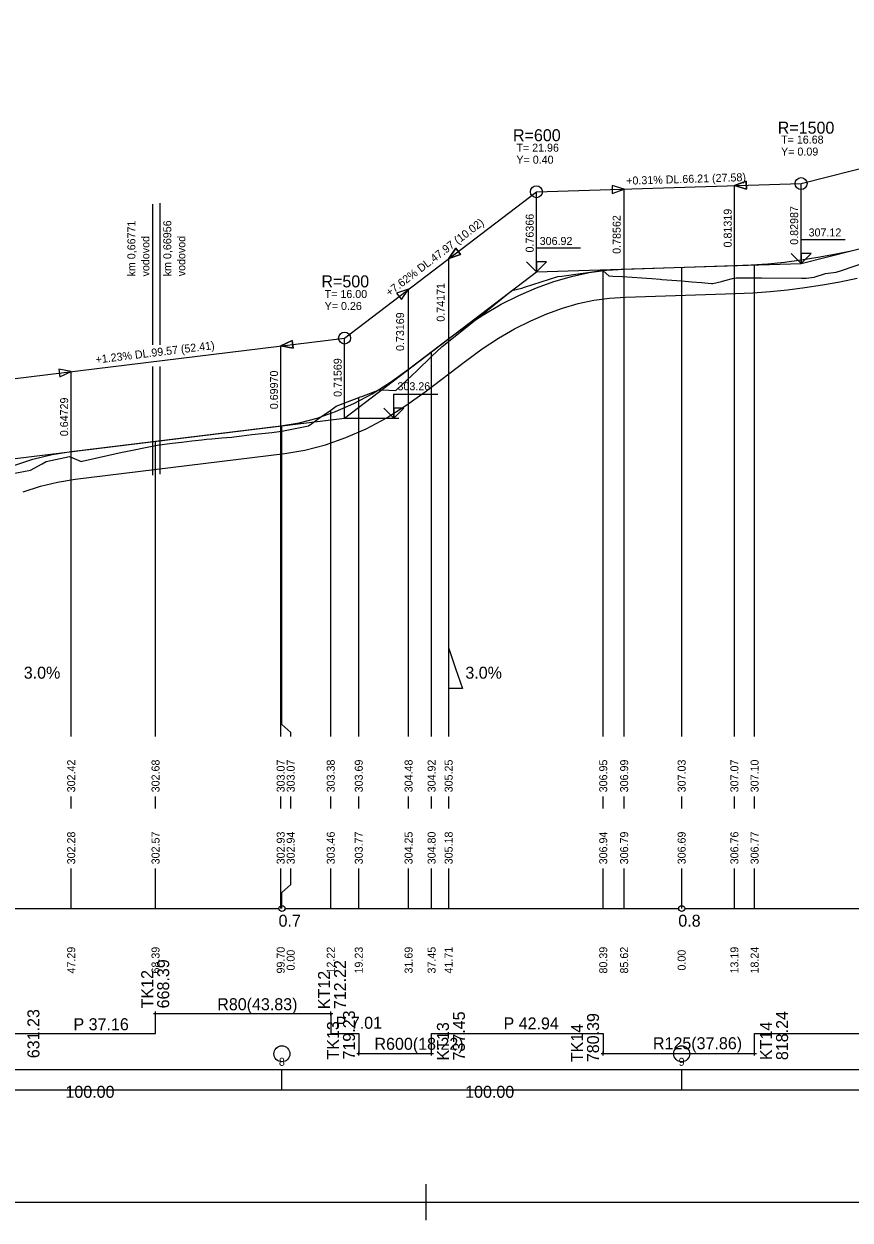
# Model space of a CAD drawing. Extents: x 1301 to 1448, y 183 to 228.
# Drawn here: x 1374.89 to 1395.56, y 182.54 to 212.44 of the extents above; entities that cross this region are included whole.
import ezdxf

# ---------------------------------------------------------------- set-up
doc = ezdxf.new("R2010")
doc.units = 0
for name, color, linetype in [('KOTA', 7, 'Continuous'), ('NOVY_STAV', 7, 'Continuous'), ('NS_OBLOUK', 7, 'Continuous'), ('REZY_PO', 7, 'Continuous'), ('SESTAVY_REZU_PO', 7, 'Continuous'), ('SKLONOVE_POMERY', 7, 'Continuous'), ('SMEROVE_POMERY', 7, 'Continuous'), ('SMEROVE_POMERY_KOD', 7, 'Continuous'), ('SVK_STAT', 7, 'Continuous'), ('u_drenaz', 7, 'Continuous'), ('u_popis', 7, 'Continuous'), ('u_pricne_rezy', 7, 'Continuous'), ('x_formát_rám', 7, 'Continuous')]:
    doc.layers.add(name, color=color, linetype=linetype)

msp = doc.modelspace()

# ---------------------------------------------------------------- linework, layer by layer
at = {"layer": 'KOTA'}
msp.add_line((1382.912, 202.588), (1384.266, 202.588), dxfattribs=at)
for points in [[(1394.33, 206.448), (1394.08, 206.698), (1394.33, 206.448), (1394.33, 207.048), (1395.43, 207.048)], [(1387.709, 206.246), (1387.459, 206.496), (1387.709, 206.246), (1387.709, 206.846), (1388.809, 206.846)], [(1394.33, 206.698), (1394.33, 206.448), (1394.58, 206.698), (1394.33, 206.698)], [(1394.33, 206.448), (1394.58, 206.698), (1394.33, 206.698)], [(1387.709, 206.496), (1387.709, 206.246), (1387.959, 206.496), (1387.709, 206.496)], [(1387.709, 206.246), (1387.959, 206.496), (1387.709, 206.496)], [(1394.33, 206.448), (1394.33, 206.448)], [(1387.709, 206.246), (1387.709, 206.246)], [(1384.145, 202.588), (1383.895, 202.838), (1384.145, 202.588), (1384.145, 203.188), (1385.245, 203.188)], [(1384.145, 202.838), (1384.145, 202.588), (1384.395, 202.838), (1384.145, 202.838)], [(1384.145, 202.588), (1384.395, 202.838), (1384.145, 202.838)], [(1384.145, 202.588), (1384.145, 202.588)]]:
    msp.add_lwpolyline(points, dxfattribs=at)
at = {"layer": 'NOVY_STAV'}
for points in [[(1371.343, 199.496), (1372.956, 201.369), (1382.912, 202.588), (1387.709, 206.246), (1394.33, 206.448), (1402.893, 208.614), (1408.521, 213.539), (1416.937, 214.971), (1425.443, 212.807)], [(1394.33, 208.448), (1402.893, 210.614)], [(1387.709, 208.246), (1394.33, 208.448)], [(1394.33, 206.448), (1394.33, 208.448)], [(1382.912, 204.588), (1387.709, 208.246)], [(1387.709, 206.246), (1387.709, 208.246)], [(1374.633, 201.402), (1375.113, 201.556), (1375.592, 201.672), (1376.072, 201.75), (1381.312, 202.392), (1381.77, 202.469), (1382.227, 202.588), (1382.684, 202.748), (1383.141, 202.951), (1383.598, 203.195), (1384.055, 203.48), (1384.512, 203.808), (1385.514, 204.572), (1385.953, 204.89), (1386.392, 205.177), (1386.831, 205.431), (1387.27, 205.654), (1387.709, 205.844), (1388.148, 206.002), (1388.587, 206.128), (1389.026, 206.222), (1389.465, 206.283), (1389.904, 206.313), (1392.662, 206.397), (1393.079, 206.416), (1393.496, 206.446), (1393.913, 206.487), (1394.33, 206.541), (1394.747, 206.606), (1395.164, 206.682), (1395.581, 206.77)], [(1372.956, 203.369), (1382.912, 204.588)], [(1382.912, 202.588), (1382.912, 204.588)]]:
    msp.add_lwpolyline(points, dxfattribs=at)
for centre in [(1394.33, 208.448), (1387.709, 208.246), (1382.912, 204.588)]:
    msp.add_circle(centre, 0.15, dxfattribs=at)
at = {"layer": 'NS_OBLOUK'}
for points in [[(1392.662, 208.397), (1392.965, 208.306), (1392.959, 208.506), (1392.662, 208.397)], [(1389.608, 208.204), (1389.905, 208.313), (1389.602, 208.404), (1389.608, 208.204)], [(1389.905, 206.313), (1389.905, 208.313)], [(1392.662, 206.397), (1392.662, 208.397)], [(1385.514, 206.572), (1385.813, 206.674), (1385.691, 206.833), (1385.514, 206.572)], [(1385.514, 204.572), (1385.514, 206.572)], [(1384.334, 205.547), (1384.512, 205.808), (1384.213, 205.706), (1384.334, 205.547)], [(1384.512, 203.808), (1384.512, 205.808)], [(1381.312, 204.392), (1381.622, 204.33), (1381.598, 204.528), (1381.312, 204.392)], [(1381.312, 202.392), (1381.312, 204.392)], [(1375.786, 203.615), (1376.072, 203.75), (1375.762, 203.813), (1375.786, 203.615)], [(1376.072, 201.75), (1376.072, 203.75)]]:
    msp.add_lwpolyline(points, dxfattribs=at)
for points in [[(1392.662, 208.397), (1392.959, 208.506), (1392.965, 208.306)], [(1389.905, 208.313), (1389.602, 208.404), (1389.608, 208.204)], [(1385.514, 206.572), (1385.691, 206.833), (1385.813, 206.674)], [(1384.512, 205.808), (1384.213, 205.706), (1384.334, 205.547)], [(1381.312, 204.392), (1381.598, 204.528), (1381.622, 204.33)], [(1376.072, 203.75), (1375.762, 203.813), (1375.786, 203.615)]]:
    msp.add_lwpolyline(points, close=True, dxfattribs=at)
at = {"layer": 'REZY_PO'}
msp.add_lwpolyline([(1374.524, 201.187), (1375.049, 201.283), (1375.343, 201.446), (1375.443, 201.501), (1376.027, 201.626), (1376.324, 201.504), (1376.343, 201.508), (1377.343, 201.73), (1377.4, 201.743), (1378.182, 201.901), (1378.182, 201.901), (1378.182, 201.901), (1378.262, 201.917), (1378.283, 201.921), (1378.343, 201.928), (1378.593, 201.958), (1378.843, 201.987), (1379.093, 202.016), (1379.343, 202.044), (1379.457, 202.057), (1379.593, 202.069), (1379.843, 202.091), (1380.093, 202.112), (1380.14, 202.115), (1380.343, 202.141), (1380.593, 202.172), (1380.843, 202.201), (1381.093, 202.229), (1381.27, 202.248), (1381.343, 202.262), (1381.593, 202.309), (1381.843, 202.359), (1382.007, 202.393), (1382.093, 202.454), (1382.343, 202.63), (1382.454, 202.709), (1382.565, 202.788), (1382.565, 202.788), (1382.565, 202.788), (1382.702, 202.885), (1383.266, 203.1), (1383.304, 203.114), (1383.343, 203.129), (1383.774, 203.296), (1383.843, 203.292), (1384.193, 203.273), (1384.343, 203.415), (1384.715, 203.769), (1385.088, 204.122), (1385.343, 204.365), (1385.351, 204.372), (1386.343, 205.171), (1387.091, 205.774), (1387.343, 205.838), (1387.415, 205.856), (1388.247, 206.124), (1388.343, 206.138), (1389.343, 206.278), (1389.367, 206.281), (1389.382, 206.269), (1389.524, 206.144), (1389.622, 206.138), (1389.862, 206.123), (1390.103, 206.107), (1390.343, 206.09), (1390.593, 206.072), (1390.807, 206.056), (1390.843, 206.053), (1391.093, 206.035), (1391.343, 206.016), (1391.343, 206.016), (1391.593, 205.996), (1391.843, 205.974), (1392.093, 205.952), (1392.12, 205.95), (1392.343, 206.003), (1392.421, 206.022), (1392.618, 206.072), (1392.708, 206.096), (1392.892, 206.095), (1393.167, 206.093), (1393.343, 206.092), (1394.343, 206.086), (1394.458, 206.086), (1394.655, 206.113), (1394.942, 206.197), (1395.209, 206.233), (1395.343, 206.278), (1396.343, 206.618)], dxfattribs=at)
at = {"layer": 'SESTAVY_REZU_PO'}
for points in [[(1371.418, 190.326), (1381.268, 190.326)], [(1381.418, 190.326), (1391.268, 190.326)], [(1391.418, 190.326), (1401.268, 190.326)]]:
    msp.add_lwpolyline(points, dxfattribs=at)
for centre in [(1381.343, 190.326), (1391.343, 190.326)]:
    msp.add_circle(centre, 0.075, dxfattribs=at)
at = {"layer": 'SKLONOVE_POMERY'}
msp.add_lwpolyline([(1385.514, 195.826), (1385.514, 196.826), (1385.514, 196.826), (1385.689, 196.326), (1385.864, 195.826), (1385.514, 195.826)], dxfattribs=at)
at = {"layer": 'SMEROVE_POMERY'}
msp.add_lwpolyline([(1374.466, 187.204), (1378.182, 187.204), (1378.182, 187.704), (1382.565, 187.704), (1382.565, 187.204), (1383.266, 187.204), (1383.266, 186.704), (1385.088, 186.704), (1385.088, 187.204), (1389.382, 187.204), (1389.382, 186.704), (1393.167, 186.704), (1393.167, 187.204), (1401.761, 187.204)], dxfattribs=at)
at = {"layer": 'SMEROVE_POMERY_KOD'}
for points in [[(1378.132, 187.704), (1378.232, 187.704)], [(1378.182, 187.654), (1378.182, 187.754)], [(1382.515, 187.704), (1382.615, 187.704)], [(1382.565, 187.654), (1382.565, 187.754)], [(1383.216, 186.704), (1383.316, 186.704)], [(1383.266, 186.654), (1383.266, 186.754)], [(1385.038, 186.704), (1385.138, 186.704)], [(1385.088, 186.654), (1385.088, 186.754)], [(1389.332, 186.704), (1389.432, 186.704)], [(1389.382, 186.654), (1389.382, 186.754)], [(1393.117, 186.704), (1393.217, 186.704)], [(1393.167, 186.654), (1393.167, 186.754)]]:
    msp.add_lwpolyline(points, dxfattribs=at)
at = {"layer": 'SVK_STAT'}
for points in [[(1391.343, 194.626), (1391.343, 206.357)], [(1392.662, 194.626), (1392.662, 206.397)], [(1393.167, 194.626), (1393.167, 206.422)], [(1389.382, 194.626), (1389.382, 206.271)], [(1389.905, 194.626), (1389.905, 206.313)], [(1385.514, 194.626), (1385.514, 204.572)], [(1385.088, 194.626), (1385.088, 204.247)], [(1384.512, 194.626), (1384.512, 203.808)], [(1383.266, 194.626), (1383.266, 203.1)], [(1382.565, 194.626), (1382.565, 202.788)], [(1381.312, 194.626), (1381.312, 202.392)], [(1381.562, 194.626), (1381.562, 194.726), (1381.343, 194.926), (1381.343, 202.397)], [(1378.182, 194.626), (1378.182, 202.009)], [(1376.072, 194.626), (1376.072, 201.75)], [(1376.072, 192.826), (1376.072, 193.126)], [(1378.182, 192.826), (1378.182, 193.126)], [(1381.312, 192.826), (1381.312, 193.126)], [(1381.562, 192.826), (1381.562, 193.126)], [(1382.565, 192.826), (1382.565, 193.126)], [(1383.266, 192.826), (1383.266, 193.126)], [(1384.512, 192.826), (1384.512, 193.126)], [(1385.088, 192.826), (1385.088, 193.126)], [(1385.514, 192.826), (1385.514, 193.126)], [(1389.382, 192.826), (1389.382, 193.126)], [(1389.905, 192.826), (1389.905, 193.126)], [(1391.343, 192.826), (1391.343, 193.126)], [(1392.662, 192.826), (1392.662, 193.126)], [(1393.167, 192.826), (1393.167, 193.126)], [(1376.072, 190.326), (1376.072, 191.326)], [(1378.182, 190.326), (1378.182, 191.326)], [(1381.312, 190.326), (1381.312, 191.326)], [(1381.343, 190.326), (1381.343, 190.726), (1381.562, 190.926), (1381.562, 191.326)], [(1382.565, 190.326), (1382.565, 191.326)], [(1383.266, 190.326), (1383.266, 191.326)], [(1384.512, 190.326), (1384.512, 191.326)], [(1385.088, 190.326), (1385.088, 191.326)], [(1385.514, 190.326), (1385.514, 191.326)], [(1389.382, 190.326), (1389.382, 191.326)], [(1389.905, 190.326), (1389.905, 191.326)], [(1391.343, 190.326), (1391.343, 191.326)], [(1392.662, 190.326), (1392.662, 191.326)], [(1393.167, 190.326), (1393.167, 191.326)]]:
    msp.add_lwpolyline(points, dxfattribs=at)
at = {"layer": 'u_drenaz'}
msp.add_lwpolyline([(1374.872, 200.743), (1375.303, 200.882), (1375.731, 200.986), (1376.17, 201.057), (1381.413, 201.699), (1381.916, 201.784), (1382.431, 201.918), (1382.942, 202.097), (1383.448, 202.321), (1383.949, 202.588), (1384.445, 202.899), (1384.928, 203.245), (1385.931, 204.01), (1386.35, 204.314), (1386.759, 204.581), (1387.165, 204.816), (1387.567, 205.02), (1387.967, 205.193), (1388.363, 205.335), (1388.757, 205.448), (1389.148, 205.532), (1389.538, 205.587), (1389.939, 205.613), (1392.688, 205.698), (1393.12, 205.717), (1393.556, 205.748), (1393.992, 205.792), (1394.428, 205.848), (1394.864, 205.915), (1395.299, 205.995), (1395.734, 206.087)], dxfattribs=at)
at = {"layer": 'u_popis'}
for points in [[(1378.114, 204.418), (1378.114, 207.932)], [(1378.299, 204.418), (1378.299, 207.955)], [(1378.114, 201.162), (1378.114, 203.877)], [(1378.299, 201.185), (1378.299, 203.878)]]:
    msp.add_lwpolyline(points, dxfattribs=at)
at = {"layer": 'u_pricne_rezy'}
for points in [[(1311.343, 185.793), (1425.461, 185.793), (1425.461, 186.293), (1311.343, 186.293), (1311.343, 185.793)], [(1381.343, 185.793), (1381.343, 186.293)], [(1391.343, 185.793), (1391.343, 186.293)]]:
    msp.add_lwpolyline(points, dxfattribs=at)
for centre in [(1381.343, 186.693), (1391.343, 186.693)]:
    msp.add_circle(centre, 0.2, dxfattribs=at)
at = {"layer": 'x_formát_rám'}
msp.add_line((1384.954, 182.537), (1384.954, 183.437), dxfattribs=at)
msp.add_lwpolyline([(1300.954, 182.987), (1447.954, 182.987), (1447.954, 227.537), (1300.954, 227.537)], close=True, dxfattribs=at)

# ---------------------------------------------------------------- texts
at = {"layer": 'KOTA'}
for s, p in [('307.12', (1394.518, 207.127)), ('306.92', (1387.791, 206.914)), ('303.26', (1384.234, 203.282))]:
    msp.add_text(s, height=0.2, dxfattribs=at).set_placement(p)
at = {"layer": 'NOVY_STAV'}
for s, rotation, p in [('+0.31% DL.66.21 (27.58)', 1.7518, (1389.958, 208.419)), (' 0.82987', 90, (1394.257, 206.845)), ('+7.62% DL.47.97 (10.02)', 37.3228, (1384.035, 205.619)), (' 0.76366', 90, (1387.641, 206.652)), ('+1.23% DL.99.57 (52.41)', 6.9848, (1376.694, 203.947)), (' 0.71569', 90, (1382.837, 203.041))]:
    msp.add_text(s, height=0.2, rotation=rotation, dxfattribs=at).set_placement(p)
at = {"layer": 'NS_OBLOUK'}
for s, height, p in [('R=1500', 0.3, (1393.746, 209.696)), ('R=600', 0.3, (1387.123, 209.507)), ('T= 16.68', 0.2, (1393.83, 209.448)), ('T= 21.96', 0.2, (1387.209, 209.246)), ('Y= 0.09', 0.2, (1393.83, 209.148)), ('Y= 0.40', 0.2, (1387.209, 208.946)), ('R=500', 0.3, (1382.331, 205.854)), ('T= 16.00', 0.2, (1382.412, 205.588)), ('Y= 0.26', 0.2, (1382.412, 205.288))]:
    msp.add_text(s, height=height, dxfattribs=at).set_placement(p)
for s, p in [(' 0.78562', (1389.817, 206.618)), (' 0.81319', (1392.594, 206.778)), (' 0.74171', (1385.414, 204.922)), (' 0.73169', (1384.399, 204.189)), (' 0.69970', (1381.244, 202.733)), (' 0.64729', (1375.994, 202.058))]:
    msp.add_text(s, height=0.2, rotation=90, dxfattribs=at).set_placement(p)
at = {"layer": 'SESTAVY_REZU_PO'}
for s, p in [('0.7', (1381.259, 189.871)), ('0.8', (1391.259, 189.871))]:
    msp.add_text(s, height=0.3, dxfattribs=at).set_placement(p)
at = {"layer": 'SKLONOVE_POMERY'}
for p in [(1374.885, 196.071), (1385.932, 196.071)]:
    msp.add_text('3.0%', height=0.3, dxfattribs=at).set_placement(p)
at = {"layer": 'SMEROVE_POMERY'}
for s, p in [('R80(43.83)', (1379.725, 187.783)), ('P 37.16', (1376.129, 187.283)), ('P 7.01', (1382.687, 187.319)), ('P 42.94', (1386.887, 187.303)), ('R600(18.22)', (1383.658, 186.793)), ('R125(37.86)', (1390.624, 186.808))]:
    msp.add_text(s, height=0.3, dxfattribs=at).set_placement(p)
at = {"layer": 'SMEROVE_POMERY_KOD'}
for s, p in [('668.39', (1378.522, 187.829)), ('712.22', (1382.946, 187.809)), ('TK12', (1378.122, 187.829)), ('KT12', (1382.546, 187.809)), ('631.23', (1375.276, 186.583)), ('719.23', (1383.17, 186.55)), ('737.45', (1385.92, 186.525)), ('780.39', (1389.275, 186.484)), ('818.24', (1394.005, 186.535)), ('TK13', (1382.77, 186.55)), ('KT13', (1385.52, 186.525)), ('TK14', (1388.875, 186.484)), ('KT14', (1393.605, 186.535))]:
    msp.add_text(s, height=0.3, rotation=90, dxfattribs=at).set_placement(p)
at = {"layer": 'SVK_STAT'}
for s, p in [(' 302.42', (1376.171, 193.156)), (' 302.68', (1378.281, 193.156)), (' 303.07', (1381.412, 193.156)), (' 303.07', (1381.662, 193.156)), (' 303.38', (1382.664, 193.156)), (' 303.69', (1383.365, 193.156)), (' 304.48', (1384.611, 193.156)), (' 304.92', (1385.187, 193.156)), (' 305.25', (1385.613, 193.156)), (' 306.95', (1389.481, 193.156)), (' 306.99', (1390.004, 193.156)), (' 307.03', (1391.442, 193.156)), (' 307.07', (1392.762, 193.156)), (' 307.10', (1393.267, 193.156)), (' 302.28', (1376.171, 191.356)), (' 302.57', (1378.281, 191.356)), (' 302.93', (1381.412, 191.356)), (' 302.94', (1381.662, 191.356)), (' 303.46', (1382.664, 191.356)), (' 303.77', (1383.365, 191.356)), (' 304.25', (1384.611, 191.356)), (' 304.80', (1385.187, 191.356)), (' 305.18', (1385.613, 191.356)), (' 306.94', (1389.481, 191.356)), (' 306.79', (1390.004, 191.356)), (' 306.69', (1391.442, 191.356)), (' 306.76', (1392.762, 191.356)), (' 306.77', (1393.267, 191.356)), (' 47.29', (1376.171, 188.626)), (' 68.39', (1378.281, 188.626)), (' 99.70', (1381.412, 188.626)), (' 12.22', (1382.664, 188.626)), (' 19.23', (1383.365, 188.626)), (' 31.69', (1384.611, 188.626)), (' 37.45', (1385.187, 188.626)), (' 41.71', (1385.613, 188.626)), (' 80.39', (1389.481, 188.626)), (' 85.62', (1390.004, 188.626)), (' 13.19', (1392.762, 188.626)), (' 18.24', (1393.267, 188.626)), ('  0.00', (1381.662, 188.626)), ('  0.00', (1391.442, 188.626))]:
    msp.add_text(s, height=0.2, rotation=90, dxfattribs=at).set_placement(p)
at = {"layer": 'u_popis'}
for s, p in [('km 0,66771', (1377.677, 206.126)), ('km 0,66956', (1378.575, 206.131)), ('vodovod', (1378.027, 206.126)), ('vodovod', (1378.925, 206.131))]:
    msp.add_text(s, height=0.2, rotation=90, dxfattribs=at).set_placement(p)
at = {"layer": 'u_pricne_rezy'}
for s, height, p in [('8', 0.2, (1381.267, 186.393)), ('9', 0.2, (1391.267, 186.393)), ('100.00', 0.3, (1375.927, 185.593)), ('100.00', 0.3, (1385.927, 185.593))]:
    msp.add_text(s, height=height, dxfattribs=at).set_placement(p)

doc.saveas('drawing.dxf')
